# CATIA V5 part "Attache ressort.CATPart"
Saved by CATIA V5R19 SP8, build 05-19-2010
Part number: Attache ressort
Revision: ANY
Definition: UNKNOWN
Nomenclature: Attache ressort
Source: Unknown
Bounding box of the stored display mesh (mm): x -4 to 4, y -3.991 to 3.991, z -3.5 to 10
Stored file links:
  D:\Documents\1_Travail\1 - ac-limoges.fr\OneDrive - ac-limoges.fr\STI2D_Turgot\2 -2I2D\3_SEQUENCE_Serre_Connectée\3- Spécificités\ITEC\EC 3 Ouverture automatique\Simulation  Ouverture Automatique\Attache ressort.CATPart
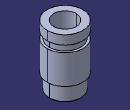
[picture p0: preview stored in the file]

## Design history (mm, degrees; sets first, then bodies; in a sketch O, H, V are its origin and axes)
Body1 "NONE" (main body)
  Solid1: solid without history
